(* Logix 5000 project; controller DNP3Outstation vendor 1 type 14 code 96 rev 21.11; software revision 21.00 *)

TASK MainTask (continuous, watchdog 500 ms) : DNP3Outstation

MODULES
   Local : vendor 1 type 14 code 96 (ICP 0, rev 21.11)
      eth : vendor 1 type 12 code 200 (Ethernet 192.168.1.129, ICP 1, rev 5.7)
         DNPS01 : vendor 309 type 12 code 5213 (Ethernet 192.168.1.162, rev 1.3, StandardDataDriven RPI 500 ms)
END_MODULES

TYPE PLX51DNPInput :
STRUCT
   Instance : STRING;
   Status : PLX51DNPStatus;
   MasterMappedStatus : BOOL[1024];
   TransactionRate : DINT;
   Temperature : REAL;
   DNP3RxPacketCount : DINT;
   DNP3TxPacketCount : DINT;
   DNP3ChecksumErrors : DINT;
   DNP3MsgTimeout : DINT;
   AuthenticationFailures : DINT;
   SessionKeyChanges : DINT;
   TagReads : DINT;
   TagWrites : DINT;
   TagConnectionFailures : DINT;
   TagErrors : DINT;
   MasterEventBufferIndex : DINT;
END_STRUCT
END_TYPE

TYPE PLX51DNPOutput :
STRUCT
   RoutingInhibited : BOOL;
END_STRUCT
END_TYPE

TYPE PLX51DNPStatus :
STRUCT
   OutstationMode : BOOL;
   MasterMode : BOOL;
   UnscheduledMode : BOOL;
   ConfigurationValid : BOOL;
   RoutingInhibited : BOOL;
   DNP3EventLogOk : BOOL;
   DNP3EventLogOverflow : BOOL;
END_STRUCT
END_TYPE

TYPE PSDNP3AnalogInput16Flag :
STRUCT
   Online : BOOL;
   Restart : BOOL;
   CommLost : BOOL;
   RemoteForced : BOOL;
   LocalForced : BOOL;
   OverRange : BOOL;
   ReferenceError : BOOL;
   EventTrigger : BOOL;
   Value : INT;
END_STRUCT
END_TYPE

TYPE PSDNP3AnalogInput32Flag :
STRUCT
   Online : BOOL;
   Restart : BOOL;
   CommLost : BOOL;
   RemoteForced : BOOL;
   LocalForced : BOOL;
   OverRange : BOOL;
   ReferenceError : BOOL;
   EventTrigger : BOOL;
   Value : DINT;
END_STRUCT
END_TYPE

TYPE PSDNP3AnalogInputRealFlag :
STRUCT
   Online : BOOL;
   Restart : BOOL;
   CommLost : BOOL;
   RemoteForced : BOOL;
   LocalForced : BOOL;
   OverRange : BOOL;
   ReferenceError : BOOL;
   EventTrigger : BOOL;
   Value : REAL;
END_STRUCT
END_TYPE

TYPE PSDNP3AnalogOutput16 :
STRUCT
   RequestPending : BOOL;
   Reserved : INT;
   Value : INT;
   Status : SINT;
END_STRUCT
END_TYPE

TYPE PSDNP3AnalogOutput32 :
STRUCT
   RequestPending : BOOL;
   Reserved : INT;
   Value : DINT;
   Status : SINT;
END_STRUCT
END_TYPE

TYPE PSDNP3AnalogOutputReal :
STRUCT
   RequestPending : BOOL;
   Reserved : INT;
   Value : REAL;
   Status : SINT;
END_STRUCT
END_TYPE

TYPE PSDNP3AnalogOutputStatus16Flag :
STRUCT
   Online : BOOL;
   Restart : BOOL;
   CommLost : BOOL;
   RemoteForced : BOOL;
   LocalForced : BOOL;
   OverRange : BOOL;
   ReferenceError : BOOL;
   EventTrigger : BOOL;
   Value : INT;
END_STRUCT
END_TYPE

TYPE PSDNP3AnalogOutputStatus32Flag :
STRUCT
   Online : BOOL;
   Restart : BOOL;
   CommLost : BOOL;
   RemoteForced : BOOL;
   LocalForced : BOOL;
   OverRange : BOOL;
   ReferenceError : BOOL;
   EventTrigger : BOOL;
   Value : DINT;
END_STRUCT
END_TYPE

TYPE PSDNP3AnalogOutputStatusRealFlag :
STRUCT
   Online : BOOL;
   Restart : BOOL;
   CommLost : BOOL;
   RemoteForced : BOOL;
   LocalForced : BOOL;
   OverRange : BOOL;
   ReferenceError : BOOL;
   EventTrigger : BOOL;
   Value : REAL;
END_STRUCT
END_TYPE

TYPE PSDNP3BinaryInputPacked :
STRUCT
   BinaryValues : SINT[32];
END_STRUCT
END_TYPE

TYPE PSDNP3BinaryInputWithFlag :
STRUCT
   Online : BOOL;
   Restart : BOOL;
   CommLost : BOOL;
   RemoteForced : BOOL;
   LocalForced : BOOL;
   ChatterFilter : BOOL;
   Reserved : BOOL;
   State : BOOL;
END_STRUCT
END_TYPE

TYPE PSDNP3BinaryOutputPacked :
STRUCT
   BinaryValues : SINT[32];
END_STRUCT
END_TYPE

TYPE PSDNP3BinaryOutputPulse :
STRUCT
   Count : SINT;
   OnTimer : TIMER;
   OffTimer : TIMER;
END_STRUCT
END_TYPE

TYPE PSDNP3BinaryOutputWithFlag :
STRUCT
   Online : BOOL;
   Restart : BOOL;
   CommLost : BOOL;
   RemoteForced : BOOL;
   LocalForced : BOOL;
   Reserved1 : BOOL;
   Reserved2 : BOOL;
   State : BOOL;
END_STRUCT
END_TYPE

TYPE PSDNP3Counter16WithFlag :
STRUCT
   Online : BOOL;
   Restart : BOOL;
   CommLost : BOOL;
   RemoteForced : BOOL;
   LocalForced : BOOL;
   RollOver : BOOL;
   Discontinuity : BOOL;
   EventTrigger : BOOL;
   Value : INT;
END_STRUCT
END_TYPE

TYPE PSDNP3Counter32WithFlag :
STRUCT
   Online : BOOL;
   Restart : BOOL;
   CommLost : BOOL;
   RemoteForced : BOOL;
   LocalForced : BOOL;
   RollOver : BOOL;
   Discontinuity : BOOL;
   EventTrigger : BOOL;
   Value : DINT;
END_STRUCT
END_TYPE

TYPE PSDNP3CounterCtrl :
STRUCT
   FreezeCounter : BOOL;
   ClearCounter : BOOL;
   TimeOfOccurrence : LINT;
END_STRUCT
END_TYPE

TYPE PSDNP3CROB :
STRUCT
   RequestPending : BOOL;
   Reserved : INT;
   ControlCode : SINT;
   Count : SINT;
   OnTime : DINT;
   OffTime : DINT;
   StatusCode : SINT;
END_STRUCT
END_TYPE

TYPE PSDNP3DoubleBinaryInputPacked :
STRUCT
   BinaryValues : SINT[32];
END_STRUCT
END_TYPE

TYPE PSDNP3DoubleBinaryInputWithFlag :
STRUCT
   Online : BOOL;
   Restart : BOOL;
   CommLost : BOOL;
   RemoteForced : BOOL;
   LocalForced : BOOL;
   ChatterFilter : BOOL;
   State0 : BOOL;
   State1 : BOOL;
END_STRUCT
END_TYPE

TYPE PSDNP3FrozenCounter16WithFlag :
STRUCT
   Online : BOOL;
   Restart : BOOL;
   CommLost : BOOL;
   RemoteForced : BOOL;
   LocalForced : BOOL;
   RollOver : BOOL;
   Discontinuity : BOOL;
   EventTrigger : BOOL;
   Value : INT;
END_STRUCT
END_TYPE

TYPE PSDNP3FrozenCounter16WithFlagTimeRev2 :
STRUCT
   Online : BOOL;
   Restart : BOOL;
   CommLost : BOOL;
   RemoteForced : BOOL;
   LocalForced : BOOL;
   RollOver : BOOL;
   Discontinuity : BOOL;
   EventTrigger : BOOL;
   Value : INT;
   Reserved : DINT;
   TimeOfOccurrence : LINT;
END_STRUCT
END_TYPE

TYPE PSDNP3FrozenCounter32WithFlag :
STRUCT
   Online : BOOL;
   Restart : BOOL;
   CommLost : BOOL;
   RemoteForced : BOOL;
   LocalForced : BOOL;
   RollOver : BOOL;
   Discontinuity : BOOL;
   EventTrigger : BOOL;
   Value : DINT;
END_STRUCT
END_TYPE

TYPE PSDNP3FrozenCounter32WithFlagTime :
STRUCT
   Online : BOOL;
   Restart : BOOL;
   CommLost : BOOL;
   RemoteForced : BOOL;
   LocalForced : BOOL;
   RollOver : BOOL;
   Discontinuity : BOOL;
   EventTrigger : BOOL;
   Value : DINT;
   TimeOfOccurrence : LINT;
END_STRUCT
END_TYPE

TYPE PSDNP3LocalKeyUpdateRequest :
STRUCT
   KeyLength : SINT;
   KeyData : SINT[32];
END_STRUCT
END_TYPE

TYPE PSDNP3MasterEvent :
STRUCT
   EvtPending : DINT;
   EvtGroup : SINT;
   EvtFlags : SINT;
   EvtSrcNodeAddress : INT;
   EvtSrcIPAddress : INT[4];
   EvtElementIndex : DINT;
   Reserved : DINT;
   EvtTimeStamp : LINT;
   EvtFloatValue : REAL;
   EvtIntegerValue : DINT;
END_STRUCT
END_TYPE

TYPE PSDNP3RemoteKeyUpdateRequest :
STRUCT
   Command : SINT;
   Option : SINT;
   DestinationNode : INT;
   IPAddress : INT[4];
   KeyData : SINT[255];
END_STRUCT
END_TYPE

ADD_ON_INSTRUCTION PSDNP3AnalogInputEvtLog16   (* revision 1.0, vendor ProSoft Technology Inc *)
VAR_IN_OUT
   DNP3Object : PSDNP3AnalogInput16Flag; {required}
END_VAR
VAR_INPUT
   Deadband : INT; {required}
   MinimumLogInterval : REAL; {required}
   ExtrernalEventTrigger : BOOL; {visible}
END_VAR
VAR_OUTPUT
   EventTriggers : DINT; {access Read Only, visible}
END_VAR
VAR
   RequestLog : BOOL; {access None}
   ExternalONS : BOOL; {access None}
   Interval : TIMER := (PRE := 1000000); {access None}
   PreviousValue : INT; {access None}
   DBRequest : BOOL; {access None}
   ExtRequest : BOOL; {access None}
   Pending : BOOL; {access None}
END_VAR

ROUTINE Logic   (* ladder *)
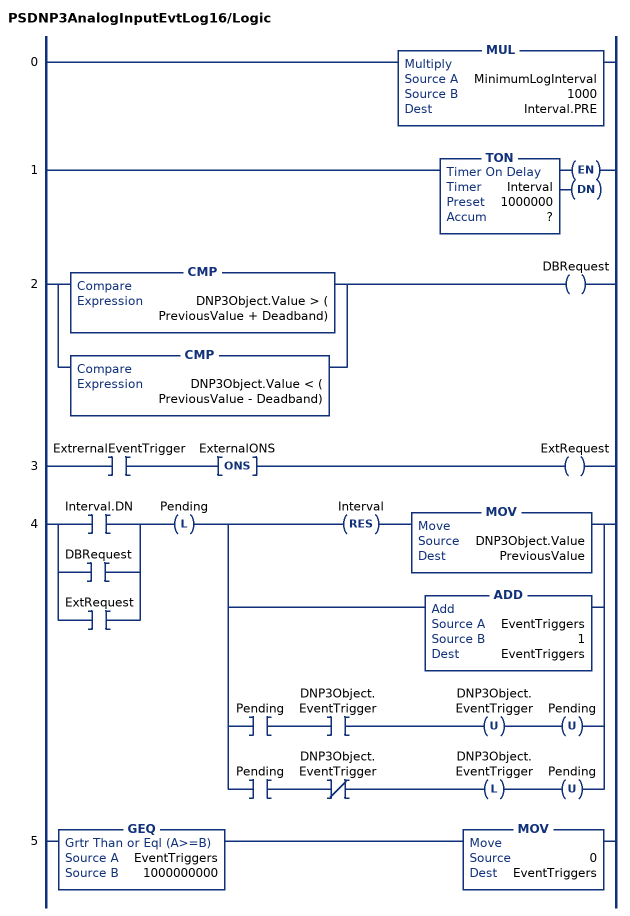
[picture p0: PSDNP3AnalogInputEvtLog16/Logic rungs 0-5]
   0: MUL(MinimumLogInterval,1000,Interval.PRE);
   1: TON(Interval,?,?);
   2: [CMP(DNP3Object.Value > ( PreviousValue + Deadband)) ,CMP(DNP3Object.Value < ( PreviousValue - Deadband)) ]OTE(DBRequest);
   3: XIC(ExtrernalEventTrigger)ONS(ExternalONS)OTE(ExtRequest);
   4: [XIC(Interval.DN) ,XIC(DBRequest) ,XIC(ExtRequest) ]OTL(Pending)[RES(Interval) MOV(DNP3Object.Value,PreviousValue) ,ADD(EventTriggers,1,EventTriggers) ,XIC(Pending) XIC(DNP3Object.EventTrigger) OTU(DNP3Object.EventTrigger) OTU(Pending) ,XIC(Pending) XIO(DNP3Object.EventTrigger) OTL(DNP3Object.EventTrigger) OTU(Pending) ];
   5: GEQ(EventTriggers,1000000000)MOV(0,EventTriggers);
END_ROUTINE
END_ADD_ON_INSTRUCTION

ADD_ON_INSTRUCTION PSDNP3AnalogInputEvtLog32   (* revision 1.0, vendor ProSoft Technology Inc *)
VAR_IN_OUT
   DNP3Object : PSDNP3AnalogInput32Flag; {required}
END_VAR
VAR_INPUT
   Deadband : DINT; {required}
   MinimumLogInterval : REAL; {required}
   ExtrernalEventTrigger : BOOL; {visible}
END_VAR
VAR_OUTPUT
   EventTriggers : DINT; {access Read Only, visible}
END_VAR
VAR
   RequestLog : BOOL; {access None}
   ExternalONS : BOOL; {access None}
   Interval : TIMER := (PRE := 1000000); {access None}
   PreviousValue : DINT; {access None}
   DBRequest : BOOL; {access None}
   ExtRequest : BOOL; {access None}
   Pending : BOOL; {access None}
END_VAR

ROUTINE Logic   (* ladder *)
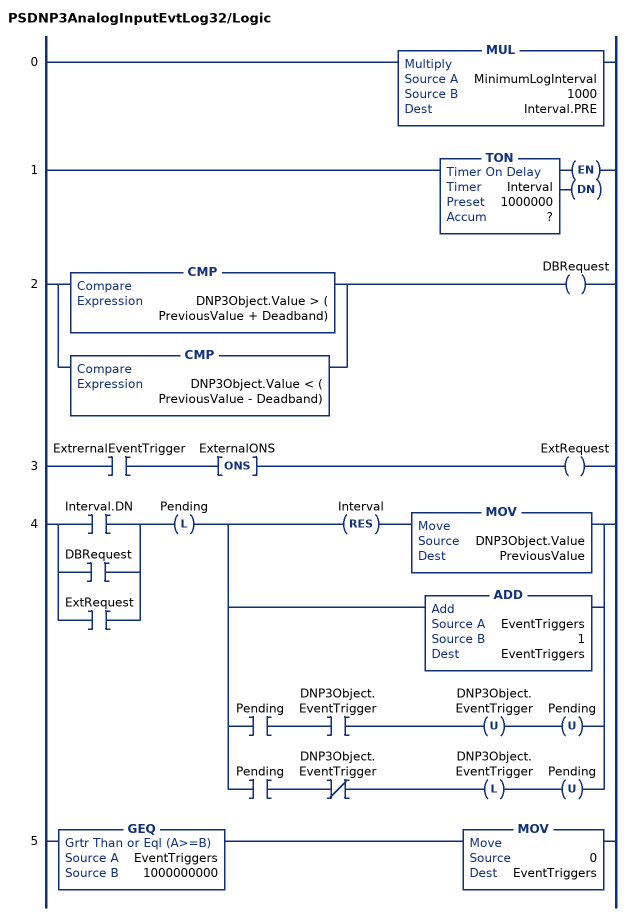
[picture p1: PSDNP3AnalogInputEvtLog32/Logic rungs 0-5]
   0: MUL(MinimumLogInterval,1000,Interval.PRE);
   1: TON(Interval,?,?);
   2: [CMP(DNP3Object.Value > ( PreviousValue + Deadband)) ,CMP(DNP3Object.Value < ( PreviousValue - Deadband)) ]OTE(DBRequest);
   3: XIC(ExtrernalEventTrigger)ONS(ExternalONS)OTE(ExtRequest);
   4: [XIC(Interval.DN) ,XIC(DBRequest) ,XIC(ExtRequest) ]OTL(Pending)[RES(Interval) MOV(DNP3Object.Value,PreviousValue) ,ADD(EventTriggers,1,EventTriggers) ,XIC(Pending) XIC(DNP3Object.EventTrigger) OTU(DNP3Object.EventTrigger) OTU(Pending) ,XIC(Pending) XIO(DNP3Object.EventTrigger) OTL(DNP3Object.EventTrigger) OTU(Pending) ];
   5: GEQ(EventTriggers,1000000000)MOV(0,EventTriggers);
END_ROUTINE
END_ADD_ON_INSTRUCTION

ADD_ON_INSTRUCTION PSDNP3AnalogInputEvtLogReal   (* revision 1.0, vendor ProSoft Technology Inc *)
VAR_IN_OUT
   DNP3Object : PSDNP3AnalogInputRealFlag; {required}
END_VAR
VAR_INPUT
   Deadband : REAL; {required}
   MinimumLogInterval : REAL; {required}
   ExtrernalEventTrigger : BOOL; {visible}
END_VAR
VAR_OUTPUT
   EventTriggers : DINT; {access Read Only, visible}
END_VAR
VAR
   RequestLog : BOOL; {access None}
   ExternalONS : BOOL; {access None}
   Interval : TIMER := (PRE := 1000000); {access None}
   PreviousValue : REAL; {access None}
   DBRequest : BOOL; {access None}
   ExtRequest : BOOL; {access None}
   Pending : BOOL; {access None}
END_VAR

ROUTINE Logic   (* ladder *)
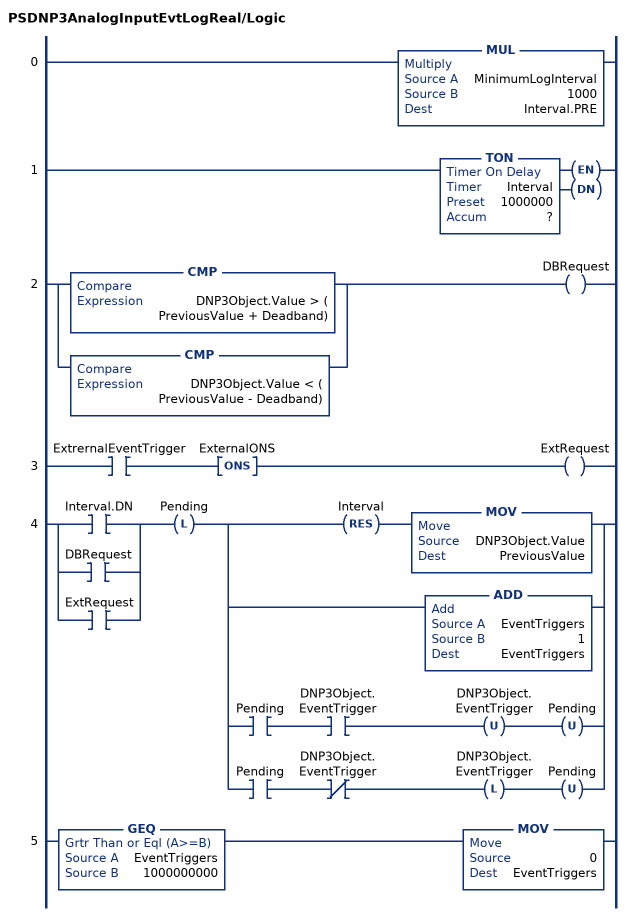
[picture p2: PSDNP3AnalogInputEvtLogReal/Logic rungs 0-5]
   0: MUL(MinimumLogInterval,1000,Interval.PRE);
   1: TON(Interval,?,?);
   2: [CMP(DNP3Object.Value > ( PreviousValue + Deadband)) ,CMP(DNP3Object.Value < ( PreviousValue - Deadband)) ]OTE(DBRequest);
   3: XIC(ExtrernalEventTrigger)ONS(ExternalONS)OTE(ExtRequest);
   4: [XIC(Interval.DN) ,XIC(DBRequest) ,XIC(ExtRequest) ]OTL(Pending)[RES(Interval) MOV(DNP3Object.Value,PreviousValue) ,ADD(EventTriggers,1,EventTriggers) ,XIC(Pending) XIC(DNP3Object.EventTrigger) OTU(DNP3Object.EventTrigger) OTU(Pending) ,XIC(Pending) XIO(DNP3Object.EventTrigger) OTL(DNP3Object.EventTrigger) OTU(Pending) ];
   5: GEQ(EventTriggers,1000000000)MOV(0,EventTriggers);
END_ROUTINE
END_ADD_ON_INSTRUCTION

ADD_ON_INSTRUCTION PSDNP3AnalogOutput16Control   (* revision 1.0, vendor ProSoft Technology Inc *)
VAR_IN_OUT
   AnalogOutputCommand : PSDNP3AnalogOutput16; {required}
   AnalogOutputStatus : PSDNP3AnalogOutputStatus16Flag; {required}
END_VAR
VAR_OUTPUT
   CurrentOutput : INT; {access Read Only, visible}
   RequestCount : DINT; {access Read Only, visible}
END_VAR
VAR_INPUT
   ResetStatistics : BOOL; {required}
END_VAR
VAR
   RequestCounter : COUNTER := (PRE := 2100000000); {access None}
END_VAR

ROUTINE Logic   (* ladder *)
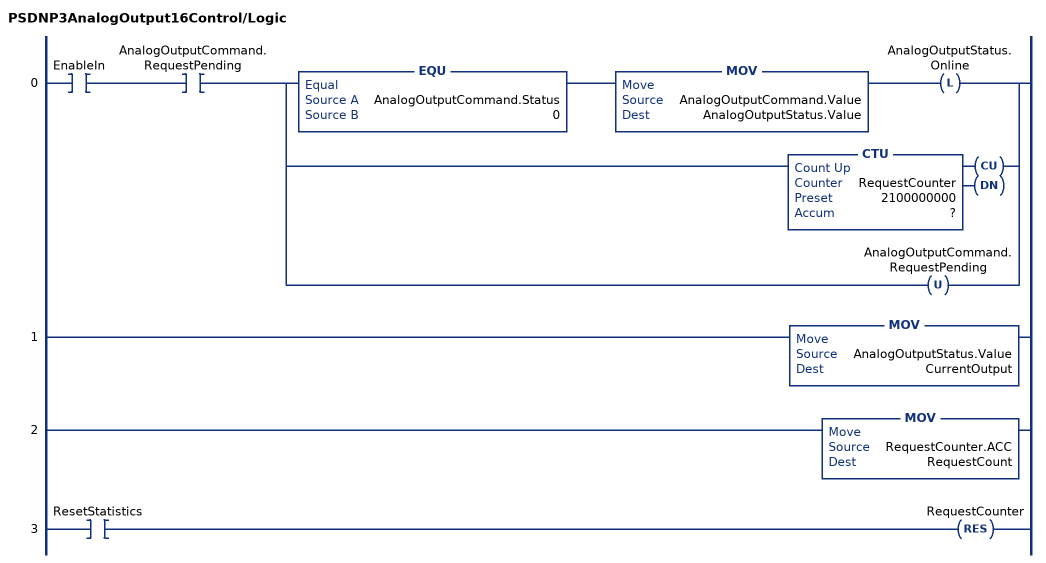
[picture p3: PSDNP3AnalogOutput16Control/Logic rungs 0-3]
   0: XIC(EnableIn)XIC(AnalogOutputCommand.RequestPending)[EQU(AnalogOutputCommand.Status,0) MOV(AnalogOutputCommand.Value,AnalogOutputStatus.Value) OTL(AnalogOutputStatus.Online) ,CTU(RequestCounter,?,?) ,OTU(AnalogOutputCommand.RequestPending) ];
   1: MOV(AnalogOutputStatus.Value,CurrentOutput);
   2: MOV(RequestCounter.ACC,RequestCount);
   3: XIC(ResetStatistics)RES(RequestCounter);
END_ROUTINE
END_ADD_ON_INSTRUCTION

ADD_ON_INSTRUCTION PSDNP3AnalogOutput32Control   (* revision 1.0, vendor ProSoft Technology Inc *)
VAR_IN_OUT
   AnalogOutputCommand : PSDNP3AnalogOutput32; {required}
   AnalogOutputStatus : PSDNP3AnalogOutputStatus32Flag; {required}
END_VAR
VAR_OUTPUT
   CurrentOutput : DINT; {access Read Only, visible}
   RequestCount : DINT; {access Read Only, visible}
END_VAR
VAR_INPUT
   ResetStatistics : BOOL; {required}
END_VAR
VAR
   RequestCounter : COUNTER := (PRE := 2100000000); {access None}
END_VAR

ROUTINE Logic   (* ladder *)
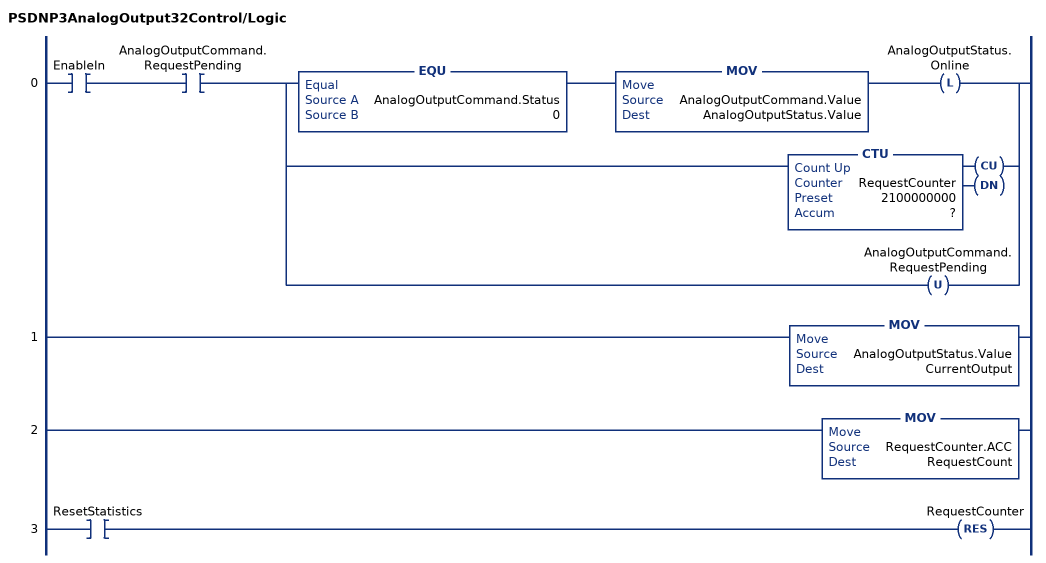
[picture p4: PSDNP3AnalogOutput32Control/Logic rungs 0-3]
   0: XIC(EnableIn)XIC(AnalogOutputCommand.RequestPending)[EQU(AnalogOutputCommand.Status,0) MOV(AnalogOutputCommand.Value,AnalogOutputStatus.Value) OTL(AnalogOutputStatus.Online) ,CTU(RequestCounter,?,?) ,OTU(AnalogOutputCommand.RequestPending) ];
   1: MOV(AnalogOutputStatus.Value,CurrentOutput);
   2: MOV(RequestCounter.ACC,RequestCount);
   3: XIC(ResetStatistics)RES(RequestCounter);
END_ROUTINE
END_ADD_ON_INSTRUCTION

ADD_ON_INSTRUCTION PSDNP3AnalogOutputRealControl   (* revision 1.0, vendor ProSoft Technology Inc *)
VAR_IN_OUT
   AnalogOutputCommand : PSDNP3AnalogOutputReal; {required}
   AnalogOutputStatus : PSDNP3AnalogOutputStatusRealFlag; {required}
END_VAR
VAR_OUTPUT
   CurrentOutput : REAL; {access Read Only, visible}
   RequestCount : DINT; {access Read Only, visible}
END_VAR
VAR_INPUT
   ResetStatistics : BOOL; {required}
END_VAR
VAR
   RequestCounter : COUNTER := (PRE := 2100000000); {access None}
END_VAR

ROUTINE Logic   (* ladder *)
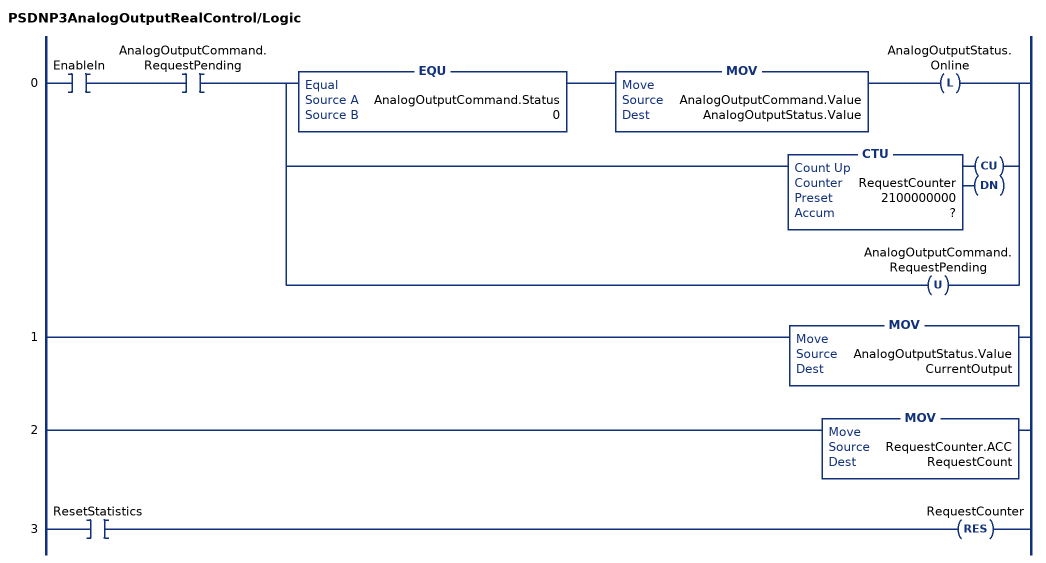
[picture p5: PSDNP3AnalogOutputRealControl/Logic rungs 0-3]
   0: XIC(EnableIn)XIC(AnalogOutputCommand.RequestPending)[EQU(AnalogOutputCommand.Status,0) MOV(AnalogOutputCommand.Value,AnalogOutputStatus.Value) OTL(AnalogOutputStatus.Online) ,CTU(RequestCounter,?,?) ,OTU(AnalogOutputCommand.RequestPending) ];
   1: MOV(AnalogOutputStatus.Value,CurrentOutput);
   2: MOV(RequestCounter.ACC,RequestCount);
   3: XIC(ResetStatistics)RES(RequestCounter);
END_ROUTINE
END_ADD_ON_INSTRUCTION

ADD_ON_INSTRUCTION PSDNP3AnalogOutputStatusEvtLog16   (* revision 1.0, vendor ProSoft Technology Inc *)
VAR_IN_OUT
   DNP3Object : PSDNP3AnalogOutputStatus32Flag; {required}
END_VAR
VAR_INPUT
   Deadband : INT; {required}
   MinimumLogInterval : REAL; {required}
   ExtrernalEventTrigger : BOOL; {visible}
END_VAR
VAR_OUTPUT
   EventTriggers : DINT; {access Read Only, visible}
END_VAR
VAR
   RequestLog : BOOL; {access None}
   ExternalONS : BOOL; {access None}
   Interval : TIMER := (PRE := 1000000); {access None}
   PreviousValue : INT; {access None}
   DBRequest : BOOL; {access None}
   ExtRequest : BOOL; {access None}
   Pending : BOOL; {access None}
END_VAR

ROUTINE Logic   (* ladder *)
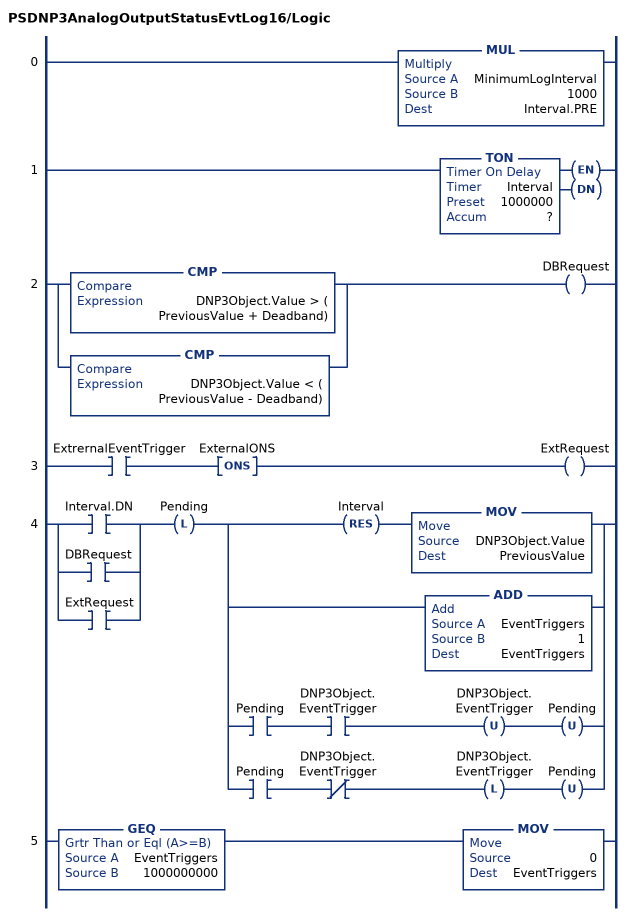
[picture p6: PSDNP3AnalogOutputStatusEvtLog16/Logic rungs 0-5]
   0: MUL(MinimumLogInterval,1000,Interval.PRE);
   1: TON(Interval,?,?);
   2: [CMP(DNP3Object.Value > ( PreviousValue + Deadband)) ,CMP(DNP3Object.Value < ( PreviousValue - Deadband)) ]OTE(DBRequest);
   3: XIC(ExtrernalEventTrigger)ONS(ExternalONS)OTE(ExtRequest);
   4: [XIC(Interval.DN) ,XIC(DBRequest) ,XIC(ExtRequest) ]OTL(Pending)[RES(Interval) MOV(DNP3Object.Value,PreviousValue) ,ADD(EventTriggers,1,EventTriggers) ,XIC(Pending) XIC(DNP3Object.EventTrigger) OTU(DNP3Object.EventTrigger) OTU(Pending) ,XIC(Pending) XIO(DNP3Object.EventTrigger) OTL(DNP3Object.EventTrigger) OTU(Pending) ];
   5: GEQ(EventTriggers,1000000000)MOV(0,EventTriggers);
END_ROUTINE
END_ADD_ON_INSTRUCTION

ADD_ON_INSTRUCTION PSDNP3AnalogOutputStatusEvtLog32   (* revision 1.0, vendor ProSoft Technology Inc *)
VAR_IN_OUT
   DNP3Object : PSDNP3AnalogOutputStatus32Flag; {required}
END_VAR
VAR_INPUT
   Deadband : DINT; {required}
   MinimumLogInterval : REAL; {required}
   ExtrernalEventTrigger : BOOL; {visible}
END_VAR
VAR_OUTPUT
   EventTriggers : DINT; {access Read Only, visible}
END_VAR
VAR
   RequestLog : BOOL; {access None}
   ExternalONS : BOOL; {access None}
   Interval : TIMER := (PRE := 1000000); {access None}
   PreviousValue : DINT; {access None}
   DBRequest : BOOL; {access None}
   ExtRequest : BOOL; {access None}
   Pending : BOOL; {access None}
END_VAR

ROUTINE Logic   (* ladder *)
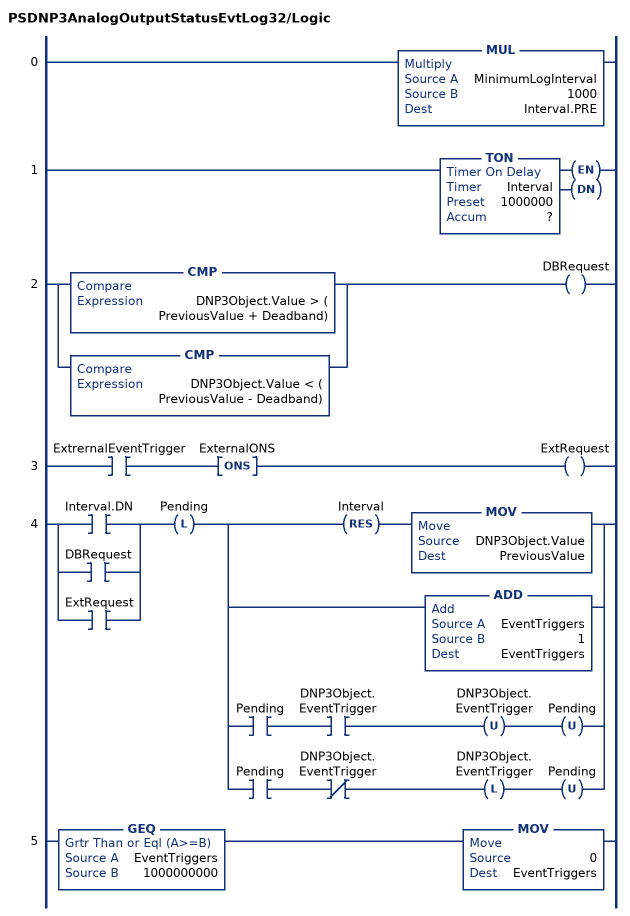
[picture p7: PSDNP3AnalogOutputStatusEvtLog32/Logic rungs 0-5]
   0: MUL(MinimumLogInterval,1000,Interval.PRE);
   1: TON(Interval,?,?);
   2: [CMP(DNP3Object.Value > ( PreviousValue + Deadband)) ,CMP(DNP3Object.Value < ( PreviousValue - Deadband)) ]OTE(DBRequest);
   3: XIC(ExtrernalEventTrigger)ONS(ExternalONS)OTE(ExtRequest);
   4: [XIC(Interval.DN) ,XIC(DBRequest) ,XIC(ExtRequest) ]OTL(Pending)[RES(Interval) MOV(DNP3Object.Value,PreviousValue) ,ADD(EventTriggers,1,EventTriggers) ,XIC(Pending) XIC(DNP3Object.EventTrigger) OTU(DNP3Object.EventTrigger) OTU(Pending) ,XIC(Pending) XIO(DNP3Object.EventTrigger) OTL(DNP3Object.EventTrigger) OTU(Pending) ];
   5: GEQ(EventTriggers,1000000000)MOV(0,EventTriggers);
END_ROUTINE
END_ADD_ON_INSTRUCTION

ADD_ON_INSTRUCTION PSDNP3AnalogOutputStatusEvtLogReal   (* revision 1.0, vendor ProSoft Technology Inc *)
VAR_IN_OUT
   DNP3Object : PSDNP3AnalogOutputStatusRealFlag; {required}
END_VAR
VAR_INPUT
   Deadband : REAL; {required}
   MinimumLogInterval : REAL; {required}
   ExtrernalEventTrigger : BOOL; {visible}
END_VAR
VAR_OUTPUT
   EventTriggers : DINT; {access Read Only, visible}
END_VAR
VAR
   RequestLog : BOOL; {access None}
   ExternalONS : BOOL; {access None}
   Interval : TIMER := (PRE := 1000000); {access None}
   PreviousValue : REAL; {access None}
   DBRequest : BOOL; {access None}
   ExtRequest : BOOL; {access None}
   Pending : BOOL; {access None}
END_VAR

ROUTINE Logic   (* ladder *)
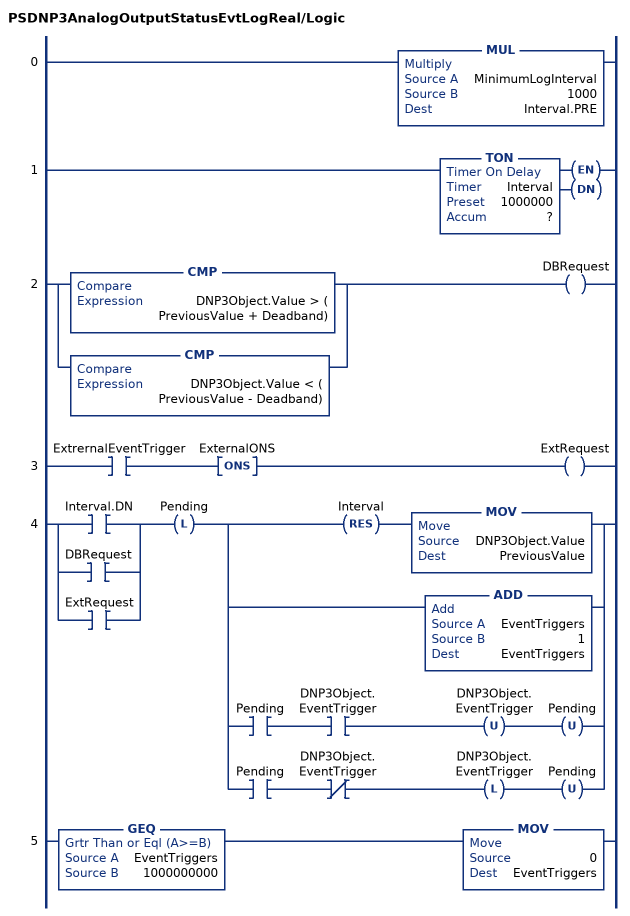
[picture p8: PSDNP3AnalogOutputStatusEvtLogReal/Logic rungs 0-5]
   0: MUL(MinimumLogInterval,1000,Interval.PRE);
   1: TON(Interval,?,?);
   2: [CMP(DNP3Object.Value > ( PreviousValue + Deadband)) ,CMP(DNP3Object.Value < ( PreviousValue - Deadband)) ]OTE(DBRequest);
   3: XIC(ExtrernalEventTrigger)ONS(ExternalONS)OTE(ExtRequest);
   4: [XIC(Interval.DN) ,XIC(DBRequest) ,XIC(ExtRequest) ]OTL(Pending)[RES(Interval) MOV(DNP3Object.Value,PreviousValue) ,ADD(EventTriggers,1,EventTriggers) ,XIC(Pending) XIC(DNP3Object.EventTrigger) OTU(DNP3Object.EventTrigger) OTU(Pending) ,XIC(Pending) XIO(DNP3Object.EventTrigger) OTL(DNP3Object.EventTrigger) OTU(Pending) ];
   5: GEQ(EventTriggers,1000000000)MOV(0,EventTriggers);
END_ROUTINE
END_ADD_ON_INSTRUCTION

ADD_ON_INSTRUCTION PSDNP3BinaryOutputCROBWithFlag   (* revision 1.0, vendor ProSoft Technology Inc *)
VAR_IN_OUT
   Control : PSDNP3CROB; {required}
   BinaryOutput : PSDNP3BinaryOutputWithFlag; {required}
END_VAR
VAR_OUTPUT
   CurrentState : BOOL; {access Read Only, visible}
   LatchOnRequestCount : DINT; {access Read Only, visible}
   LatchOffRequestCount : DINT; {access Read Only, visible}
   PulseOnRequestCount : DINT; {access Read Only, visible}
   PulseOffRequestCount : DINT; {access Read Only, visible}
   CurrentPulseCount : DINT; {access Read Only, visible}
   CurrentPulseTarget : DINT; {access Read Only, visible}
END_VAR
VAR_INPUT
   ResetStatistics : BOOL; {required}
END_VAR
VAR
   PulseCounter : COUNTER := (PRE := 100); {access None}
   PulseTimer1 : TIMER := (PRE := 1000); {access None}
   PulseTimer2 : TIMER := (PRE := 1000); {access None}
   PulseOn : BOOL; {access None}
   PulseOff : BOOL; {access None}
   PulseOffRequestCounter : COUNTER := (PRE := 2100000000); {access None}
   PulseOnRequestCounter : COUNTER := (PRE := 2100000000); {access None}
   LatchOffRequestCounter : COUNTER := (PRE := 2100000000); {access None}
   LatchOnRequestCounter : COUNTER := (PRE := 2100000000); {access None}
END_VAR

ROUTINE Logic   (* ladder *)
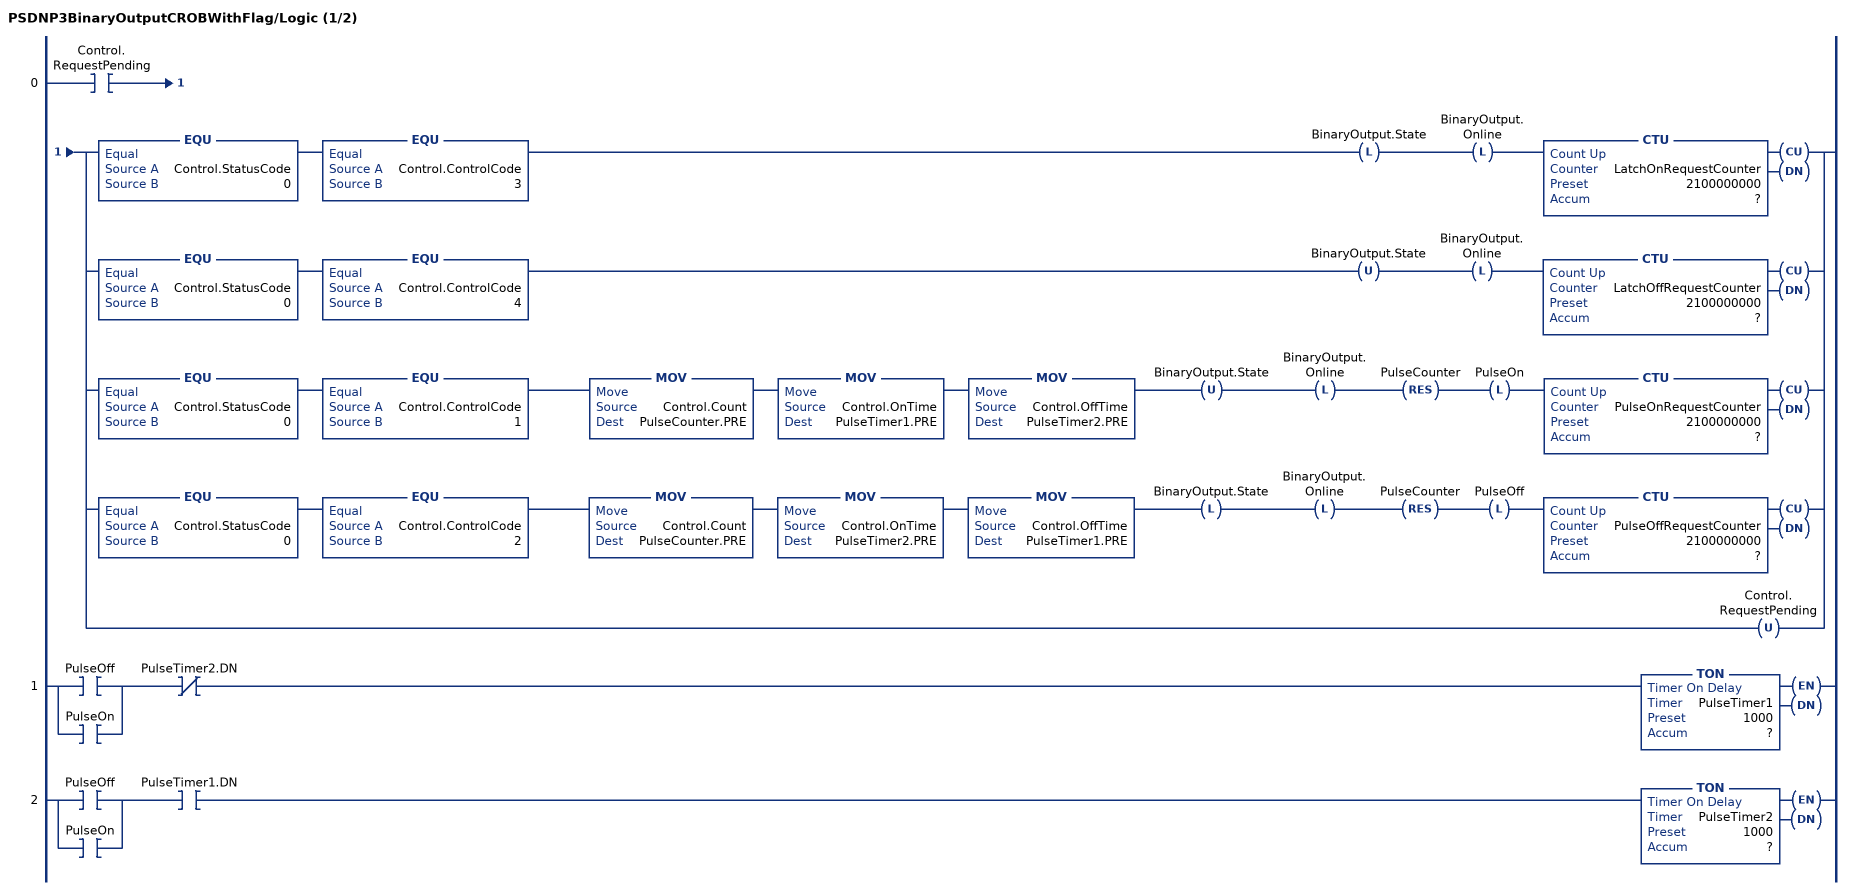
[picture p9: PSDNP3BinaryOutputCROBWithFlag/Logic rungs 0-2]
   0: XIC(Control.RequestPending)[EQU(Control.StatusCode,0) EQU(Control.ControlCode,3) OTL(BinaryOutput.State) OTL(BinaryOutput.Online) CTU(LatchOnRequestCounter,?,?) ,EQU(Control.StatusCode,0) EQU(Control.ControlCode,4) OTU(BinaryOutput.State) OTL(BinaryOutput.Online) CTU(LatchOffRequestCounter,?,?) ,EQU(Control.StatusCode,0) EQU(Control.ControlCode,1) MOV(Control.Count,PulseCounter.PRE) MOV(Control.OnTime,PulseTimer1.PRE) MOV(Control.OffTime,PulseTimer2.PRE) OTU(BinaryOutput.State) OTL(BinaryOutput.Online) RES(PulseCounter) OTL(PulseOn) CTU(PulseOnRequestCounter,?,?) ,EQU(Control.StatusCode,0) EQU(Control.ControlCode,2) MOV(Control.Count,PulseCounter.PRE) MOV(Control.OnTime,PulseTimer2.PRE) MOV(Control.OffTime,PulseTimer1.PRE) OTL(BinaryOutput.State) OTL(BinaryOutput.Online) RES(PulseCounter) OTL(PulseOff) CTU(PulseOffRequestCounter,?,?) ,OTU(Control.RequestPending) ];
   1: [XIC(PulseOff) ,XIC(PulseOn) ]XIO(PulseTimer2.DN)TON(PulseTimer1,?,?);
   2: [XIC(PulseOff) ,XIC(PulseOn) ]XIC(PulseTimer1.DN)TON(PulseTimer2,?,?);
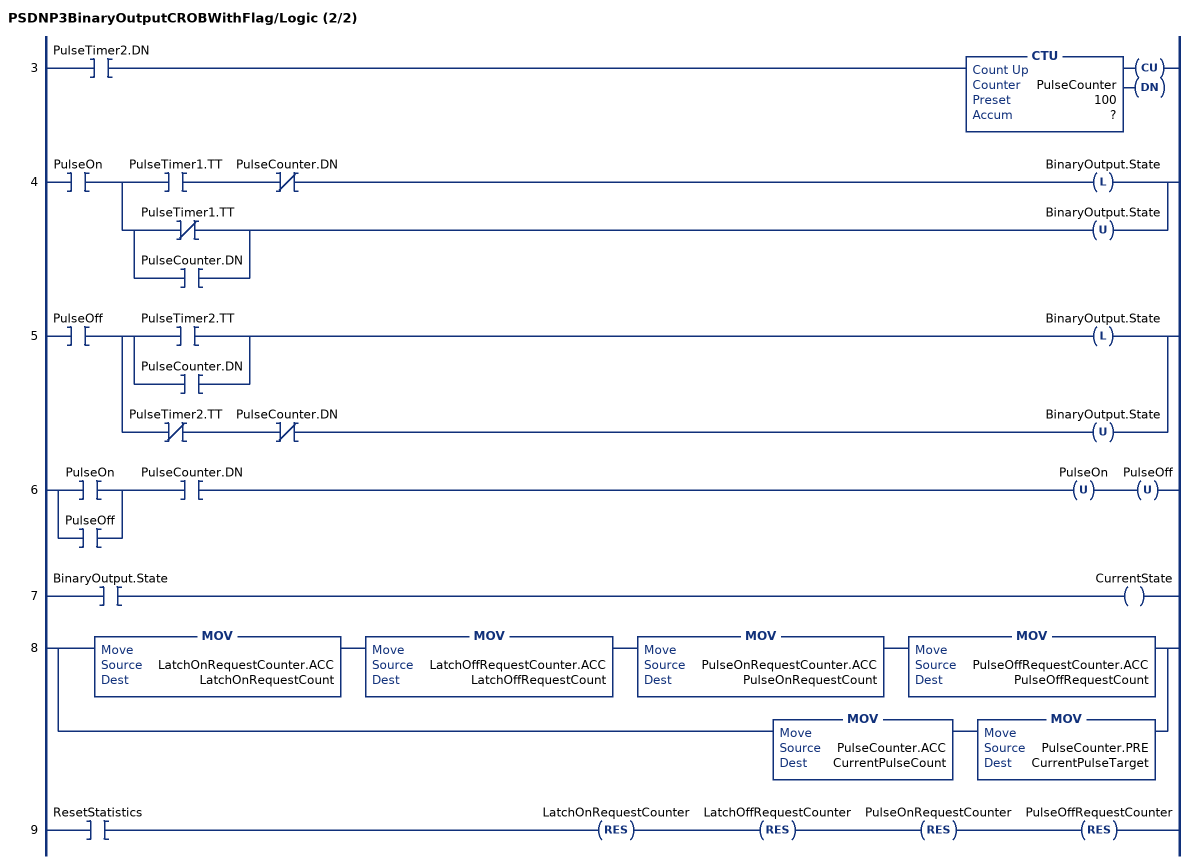
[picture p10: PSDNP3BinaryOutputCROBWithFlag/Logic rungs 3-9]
   3: XIC(PulseTimer2.DN)CTU(PulseCounter,?,?);
   4: XIC(PulseOn)[XIC(PulseTimer1.TT) XIO(PulseCounter.DN) OTL(BinaryOutput.State) ,[XIO(PulseTimer1.TT) ,XIC(PulseCounter.DN) ] OTU(BinaryOutput.State) ];
   5: XIC(PulseOff)[[XIC(PulseTimer2.TT) ,XIC(PulseCounter.DN) ] OTL(BinaryOutput.State) ,XIO(PulseTimer2.TT) XIO(PulseCounter.DN) OTU(BinaryOutput.State) ];
   6: [XIC(PulseOn) ,XIC(PulseOff) ]XIC(PulseCounter.DN)OTU(PulseOn)OTU(PulseOff);
   7: XIC(BinaryOutput.State)OTE(CurrentState);
   8: [MOV(LatchOnRequestCounter.ACC,LatchOnRequestCount) MOV(LatchOffRequestCounter.ACC,LatchOffRequestCount) MOV(PulseOnRequestCounter.ACC,PulseOnRequestCount) MOV(PulseOffRequestCounter.ACC,PulseOffRequestCount) ,MOV(PulseCounter.ACC,CurrentPulseCount) MOV(PulseCounter.PRE,CurrentPulseTarget) ];
   9: XIC(ResetStatistics)RES(LatchOnRequestCounter)RES(LatchOffRequestCounter)RES(PulseOnRequestCounter)RES(PulseOffRequestCounter);
END_ROUTINE
END_ADD_ON_INSTRUCTION

ADD_ON_INSTRUCTION PSDNP3CounterControl16   (* revision 1.0, vendor ProSoft Technology Inc *)
VAR_IN_OUT
   Control : PSDNP3CounterCtrl; {required}
   Counter : INT; {required}
   FrozenCounter : INT; {required}
END_VAR
VAR_OUTPUT
   CurrentCountValue : DINT; {access Read Only, visible}
   FrozenCountValue : DINT; {access Read Only, visible}
   ClearRequestCount : DINT; {visible}
   FreezeRequestCount : DINT; {access Read Only, visible}
END_VAR
VAR_INPUT
   ResetStatistics : BOOL; {required}
END_VAR
VAR_OUTPUT
   FreezeAction : BOOL; {access Read Only, visible}
   ClearAction : BOOL; {access Read Only, visible}
END_VAR
VAR
   FreezeRequestCounter : COUNTER := (PRE := 2100000000); {access None}
   ClearRequestCounter : COUNTER := (PRE := 2100000000); {access None}
END_VAR

ROUTINE Logic   (* ladder *)
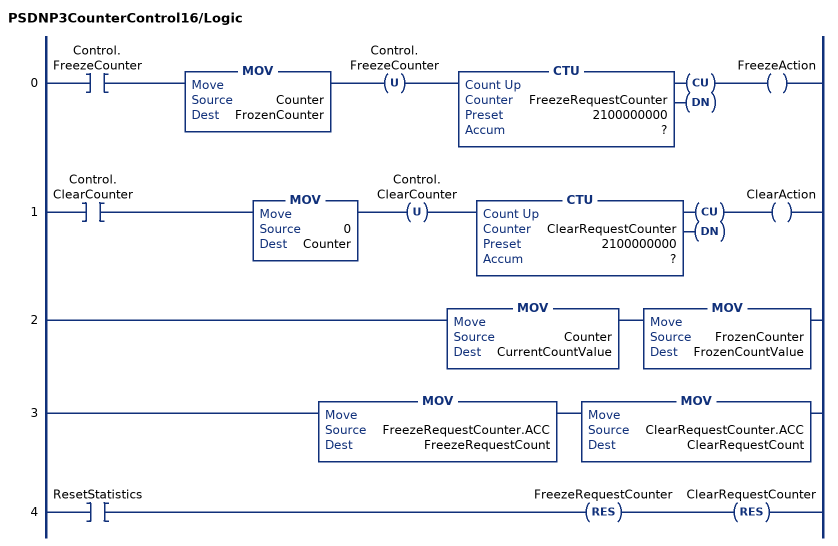
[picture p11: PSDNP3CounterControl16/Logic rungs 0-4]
   0: XIC(Control.FreezeCounter)MOV(Counter,FrozenCounter)OTU(Control.FreezeCounter)CTU(FreezeRequestCounter,?,?)OTE(FreezeAction);
   1: XIC(Control.ClearCounter)MOV(0,Counter)OTU(Control.ClearCounter)CTU(ClearRequestCounter,?,?)OTE(ClearAction);
   2: MOV(Counter,CurrentCountValue)MOV(FrozenCounter,FrozenCountValue);
   3: MOV(FreezeRequestCounter.ACC,FreezeRequestCount)MOV(ClearRequestCounter.ACC,ClearRequestCount);
   4: XIC(ResetStatistics)RES(FreezeRequestCounter)RES(ClearRequestCounter);
END_ROUTINE
END_ADD_ON_INSTRUCTION

ADD_ON_INSTRUCTION PSDNP3CounterControl16Flag   (* revision 1.0, vendor ProSoft Technology Inc *)
VAR_IN_OUT
   Control : PSDNP3CounterCtrl; {required}
   Counter : PSDNP3Counter16WithFlag; {required}
   FrozenCounter : PSDNP3FrozenCounter16WithFlag; {required}
END_VAR
VAR_OUTPUT
   CurrentCountValue : DINT; {access Read Only, visible}
   FrozenCountValue : DINT; {access Read Only, visible}
   ClearRequestCount : DINT; {visible}
   FreezeRequestCount : DINT; {access Read Only, visible}
END_VAR
VAR_INPUT
   ResetStatistics : BOOL; {required}
END_VAR
VAR_OUTPUT
   FreezeAction : BOOL; {access Read Only, visible}
   ClearAction : BOOL; {access Read Only, visible}
END_VAR
VAR
   FreezeRequestCounter : COUNTER := (PRE := 2100000000); {access None}
   ClearRequestCounter : COUNTER := (PRE := 2100000000); {access None}
END_VAR

ROUTINE Logic   (* ladder *)
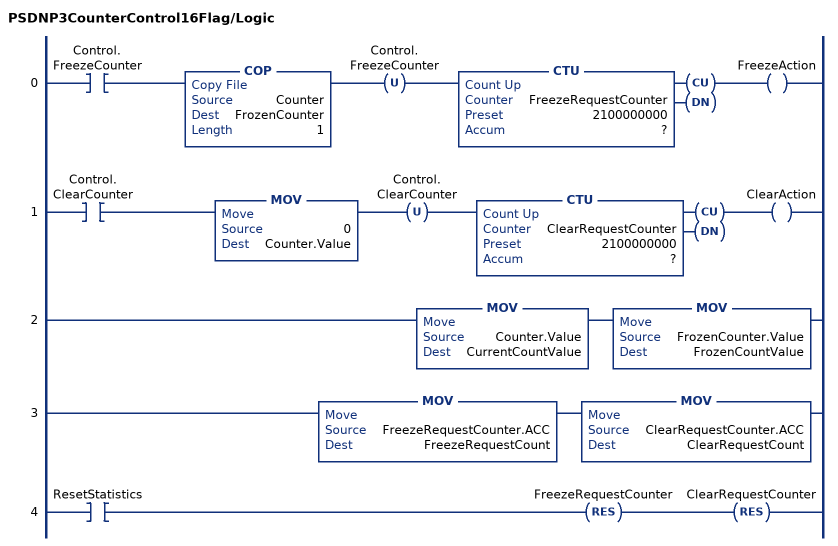
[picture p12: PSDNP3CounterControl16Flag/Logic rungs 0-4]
   0: XIC(Control.FreezeCounter)COP(Counter,FrozenCounter,1)OTU(Control.FreezeCounter)CTU(FreezeRequestCounter,?,?)OTE(FreezeAction);
   1: XIC(Control.ClearCounter)MOV(0,Counter.Value)OTU(Control.ClearCounter)CTU(ClearRequestCounter,?,?)OTE(ClearAction);
   2: MOV(Counter.Value,CurrentCountValue)MOV(FrozenCounter.Value,FrozenCountValue);
   3: MOV(FreezeRequestCounter.ACC,FreezeRequestCount)MOV(ClearRequestCounter.ACC,ClearRequestCount);
   4: XIC(ResetStatistics)RES(FreezeRequestCounter)RES(ClearRequestCounter);
END_ROUTINE
END_ADD_ON_INSTRUCTION

ADD_ON_INSTRUCTION PSDNP3CounterControl16FlagTime   (* revision 1.0, vendor ProSoft Technology Inc *)
VAR_IN_OUT
   Control : PSDNP3CounterCtrl; {required}
   Counter : PSDNP3Counter16WithFlag; {required}
   FrozenCounter : PSDNP3FrozenCounter16WithFlagTimeRev2; {required}
END_VAR
VAR_OUTPUT
   CurrentCountValue : DINT; {access Read Only, visible}
   FrozenCountValue : DINT; {access Read Only, visible}
   ClearRequestCount : DINT; {visible}
   FreezeRequestCount : DINT; {access Read Only, visible}
END_VAR
VAR_INPUT
   ResetStatistics : BOOL; {required}
END_VAR
VAR_OUTPUT
   FreezeAction : BOOL; {access Read Only, visible}
   ClearAction : BOOL; {access Read Only, visible}
END_VAR
VAR
   FreezeRequestCounter : COUNTER := (PRE := 2100000000); {access None}
   ClearRequestCounter : COUNTER := (PRE := 2100000000); {access None}
END_VAR

ROUTINE Logic   (* ladder *)
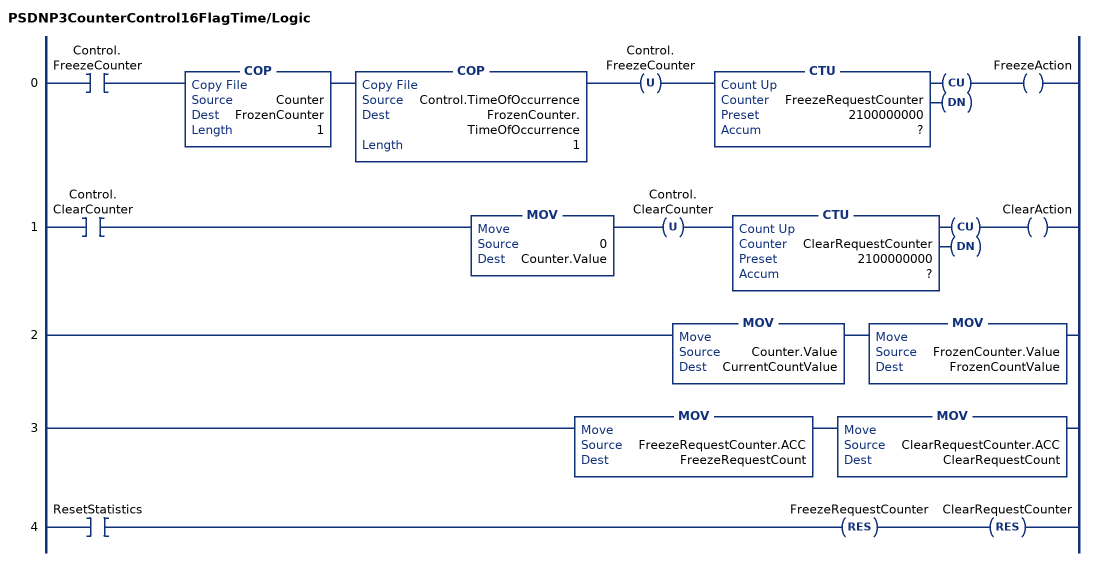
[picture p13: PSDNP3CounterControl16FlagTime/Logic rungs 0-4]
   0: XIC(Control.FreezeCounter)COP(Counter,FrozenCounter,1)COP(Control.TimeOfOccurrence,FrozenCounter.TimeOfOccurrence,1)OTU(Control.FreezeCounter)CTU(FreezeRequestCounter,?,?)OTE(FreezeAction);
   1: XIC(Control.ClearCounter)MOV(0,Counter.Value)OTU(Control.ClearCounter)CTU(ClearRequestCounter,?,?)OTE(ClearAction);
   2: MOV(Counter.Value,CurrentCountValue)MOV(FrozenCounter.Value,FrozenCountValue);
   3: MOV(FreezeRequestCounter.ACC,FreezeRequestCount)MOV(ClearRequestCounter.ACC,ClearRequestCount);
   4: XIC(ResetStatistics)RES(FreezeRequestCounter)RES(ClearRequestCounter);
END_ROUTINE
END_ADD_ON_INSTRUCTION

ADD_ON_INSTRUCTION PSDNP3CounterControl32   (* revision 1.0, vendor ProSoft Technology Inc *)
VAR_IN_OUT
   Control : PSDNP3CounterCtrl; {required}
   Counter : DINT; {required}
   FrozenCounter : DINT; {required}
END_VAR
VAR_OUTPUT
   CurrentCountValue : DINT; {access Read Only, visible}
   FrozenCountValue : DINT; {access Read Only, visible}
   ClearRequestCount : DINT; {visible}
   FreezeRequestCount : DINT; {access Read Only, visible}
END_VAR
VAR_INPUT
   ResetStatistics : BOOL; {required}
END_VAR
VAR_OUTPUT
   FreezeAction : BOOL; {access Read Only, visible}
   ClearAction : BOOL; {access Read Only, visible}
END_VAR
VAR
   FreezeRequestCounter : COUNTER := (PRE := 2100000000); {access None}
   ClearRequestCounter : COUNTER := (PRE := 2100000000); {access None}
END_VAR

ROUTINE Logic   (* ladder *)
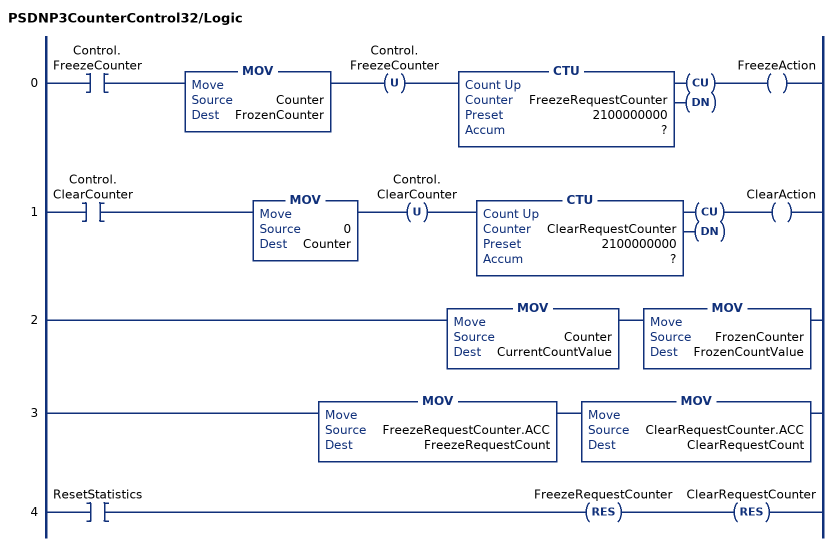
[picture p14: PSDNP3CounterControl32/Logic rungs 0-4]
   0: XIC(Control.FreezeCounter)MOV(Counter,FrozenCounter)OTU(Control.FreezeCounter)CTU(FreezeRequestCounter,?,?)OTE(FreezeAction);
   1: XIC(Control.ClearCounter)MOV(0,Counter)OTU(Control.ClearCounter)CTU(ClearRequestCounter,?,?)OTE(ClearAction);
   2: MOV(Counter,CurrentCountValue)MOV(FrozenCounter,FrozenCountValue);
   3: MOV(FreezeRequestCounter.ACC,FreezeRequestCount)MOV(ClearRequestCounter.ACC,ClearRequestCount);
   4: XIC(ResetStatistics)RES(FreezeRequestCounter)RES(ClearRequestCounter);
END_ROUTINE
END_ADD_ON_INSTRUCTION

ADD_ON_INSTRUCTION PSDNP3CounterControl32Flag   (* revision 1.0, vendor ProSoft Technology Inc *)
VAR_IN_OUT
   Control : PSDNP3CounterCtrl; {required}
   Counter : PSDNP3Counter32WithFlag; {required}
   FrozenCounter : PSDNP3FrozenCounter32WithFlag; {required}
END_VAR
VAR_OUTPUT
   CurrentCountValue : DINT; {access Read Only, visible}
   FrozenCountValue : DINT; {access Read Only, visible}
   ClearRequestCount : DINT; {visible}
   FreezeRequestCount : DINT; {access Read Only, visible}
END_VAR
VAR_INPUT
   ResetStatistics : BOOL; {required}
END_VAR
VAR_OUTPUT
   FreezeAction : BOOL; {access Read Only, visible}
   ClearAction : BOOL; {access Read Only, visible}
END_VAR
VAR
   FreezeRequestCounter : COUNTER := (PRE := 2100000000); {access None}
   ClearRequestCounter : COUNTER := (PRE := 2100000000); {access None}
END_VAR

ROUTINE Logic   (* ladder *)
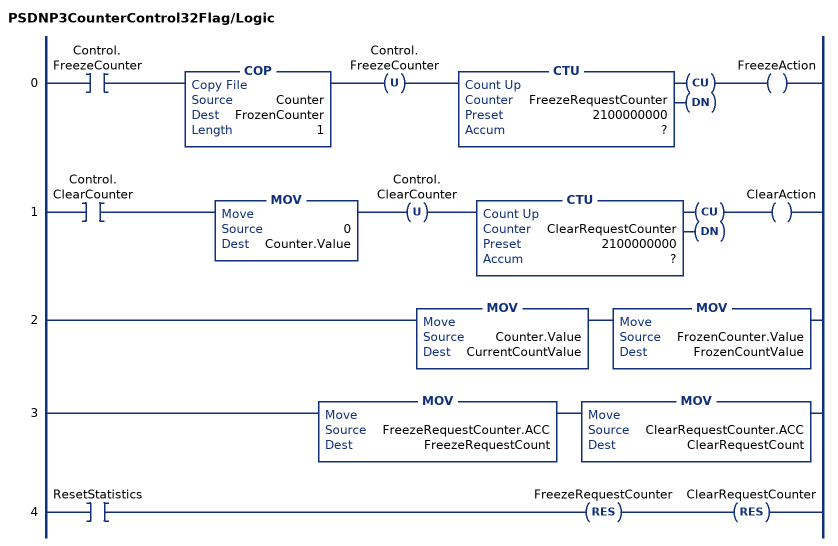
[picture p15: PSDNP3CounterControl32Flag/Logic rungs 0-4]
   0: XIC(Control.FreezeCounter)COP(Counter,FrozenCounter,1)OTU(Control.FreezeCounter)CTU(FreezeRequestCounter,?,?)OTE(FreezeAction);
   1: XIC(Control.ClearCounter)MOV(0,Counter.Value)OTU(Control.ClearCounter)CTU(ClearRequestCounter,?,?)OTE(ClearAction);
   2: MOV(Counter.Value,CurrentCountValue)MOV(FrozenCounter.Value,FrozenCountValue);
   3: MOV(FreezeRequestCounter.ACC,FreezeRequestCount)MOV(ClearRequestCounter.ACC,ClearRequestCount);
   4: XIC(ResetStatistics)RES(FreezeRequestCounter)RES(ClearRequestCounter);
END_ROUTINE
END_ADD_ON_INSTRUCTION

ADD_ON_INSTRUCTION PSDNP3CounterControl32FlagTime   (* revision 1.0, vendor ProSoft Technology Inc *)
VAR_IN_OUT
   Control : PSDNP3CounterCtrl; {required}
   Counter : PSDNP3Counter32WithFlag; {required}
   FrozenCounter : PSDNP3FrozenCounter32WithFlagTime; {required}
END_VAR
VAR_OUTPUT
   CurrentCountValue : DINT; {access Read Only, visible}
   FrozenCountValue : DINT; {access Read Only, visible}
   ClearRequestCount : DINT; {visible}
   FreezeRequestCount : DINT; {access Read Only, visible}
END_VAR
VAR_INPUT
   ResetStatistics : BOOL; {required}
END_VAR
VAR_OUTPUT
   FreezeAction : BOOL; {access Read Only, visible}
   ClearAction : BOOL; {access Read Only, visible}
END_VAR
VAR
   FreezeRequestCounter : COUNTER; {access None}
   ClearRequestCounter : COUNTER; {access None}
END_VAR

ROUTINE Logic   (* ladder *)
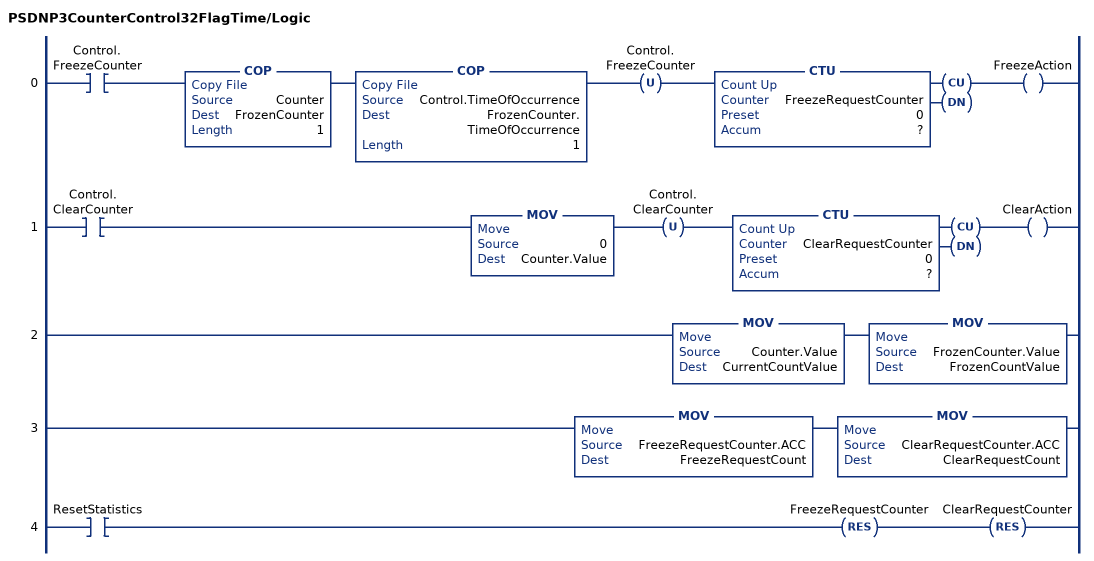
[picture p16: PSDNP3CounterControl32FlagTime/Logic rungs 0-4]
   0: XIC(Control.FreezeCounter)COP(Counter,FrozenCounter,1)COP(Control.TimeOfOccurrence,FrozenCounter.TimeOfOccurrence,1)OTU(Control.FreezeCounter)CTU(FreezeRequestCounter,?,?)OTE(FreezeAction);
   1: XIC(Control.ClearCounter)MOV(0,Counter.Value)OTU(Control.ClearCounter)CTU(ClearRequestCounter,?,?)OTE(ClearAction);
   2: MOV(Counter.Value,CurrentCountValue)MOV(FrozenCounter.Value,FrozenCountValue);
   3: MOV(FreezeRequestCounter.ACC,FreezeRequestCount)MOV(ClearRequestCounter.ACC,ClearRequestCount);
   4: XIC(ResetStatistics)RES(FreezeRequestCounter)RES(ClearRequestCounter);
END_ROUTINE
END_ADD_ON_INSTRUCTION

ADD_ON_INSTRUCTION PSDNP3CounterEvtLog16   (* revision 1.0, vendor ProSoft Technology Inc *)
VAR_IN_OUT
   DNP3Object : PSDNP3Counter16WithFlag; {required}
END_VAR
VAR_INPUT
   Deadband : INT; {required}
   MinimumLogInterval : REAL; {required}
   ExtrernalEventTrigger : BOOL; {visible}
END_VAR
VAR_OUTPUT
   EventTriggers : DINT; {access Read Only, visible}
END_VAR
VAR
   RequestLog : BOOL; {access None}
   ExternalONS : BOOL; {access None}
   Interval : TIMER := (PRE := 1000000); {access None}
   PreviousValue : INT; {access None}
   DBRequest : BOOL; {access None}
   ExtRequest : BOOL; {access None}
   Pending : BOOL; {access None}
END_VAR

ROUTINE Logic   (* ladder *)
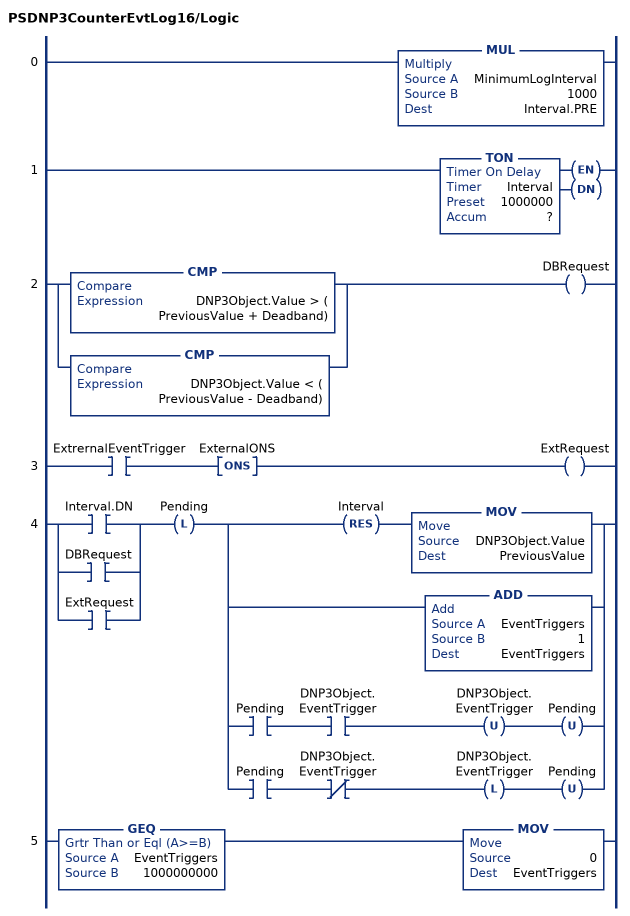
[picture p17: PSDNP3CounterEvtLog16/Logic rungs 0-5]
   0: MUL(MinimumLogInterval,1000,Interval.PRE);
   1: TON(Interval,?,?);
   2: [CMP(DNP3Object.Value > ( PreviousValue + Deadband)) ,CMP(DNP3Object.Value < ( PreviousValue - Deadband)) ]OTE(DBRequest);
   3: XIC(ExtrernalEventTrigger)ONS(ExternalONS)OTE(ExtRequest);
   4: [XIC(Interval.DN) ,XIC(DBRequest) ,XIC(ExtRequest) ]OTL(Pending)[RES(Interval) MOV(DNP3Object.Value,PreviousValue) ,ADD(EventTriggers,1,EventTriggers) ,XIC(Pending) XIC(DNP3Object.EventTrigger) OTU(DNP3Object.EventTrigger) OTU(Pending) ,XIC(Pending) XIO(DNP3Object.EventTrigger) OTL(DNP3Object.EventTrigger) OTU(Pending) ];
   5: GEQ(EventTriggers,1000000000)MOV(0,EventTriggers);
END_ROUTINE
END_ADD_ON_INSTRUCTION
